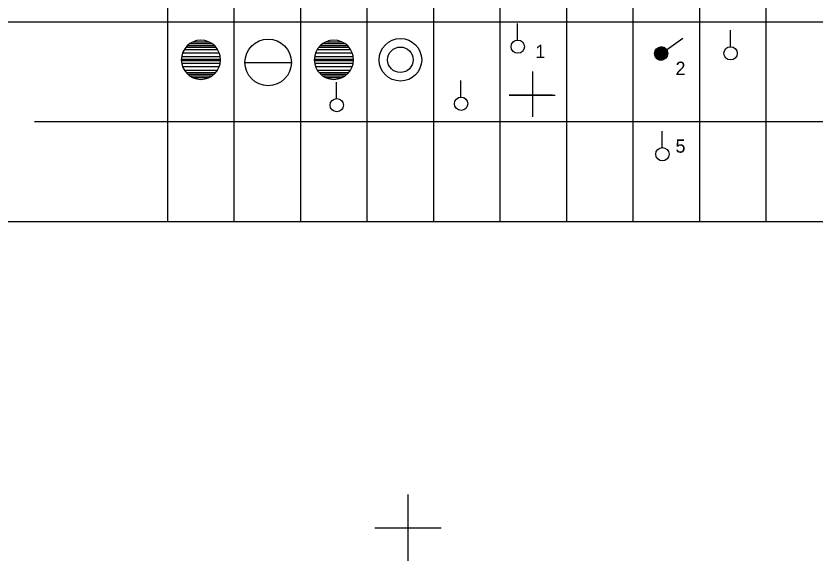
# Model space of a CAD drawing. Extents: x -28 to 822, y 61 to 665.
# Drawn here: x 337.9 to 458, y 60.7 to 142.6 of the extents above; entities that cross this region are included whole.
import ezdxf

# ---------------------------------------------------------------- set-up
doc = ezdxf.new("R2010")
doc.units = 0
doc.layers.add('KOLEJIŠTĚ', color=7, linetype='Continuous')
doc.layers.add('Vrstva 60', color=7, linetype='Continuous')

# ---------------------------------------------------------------- blocks, each defined once
blk = doc.blocks.new('HR6')
for p, q in [((-1.304, 1.895), (1.304, 1.895)), ((-0.95, 2.095), (0.95, 2.095)), ((-1.962, 1.2), (1.962, 1.2)), ((-1.748, 1.495), (1.748, 1.495)), ((-1.555, 1.695), (1.555, 1.695)), ((-2.265, 0.4), (2.265, 0.4)), ((-2.2, 0.09), (2.2, 0.09)), ((-2.156, 0.8), (2.156, 0.8)), ((-2.265, -0.4), (2.265, -0.4)), ((-2.2, -0.09), (2.2, -0.09)), ((-2.156, -0.8), (2.156, -0.8)), ((-1.962, -1.2), (1.962, -1.2)), ((-1.748, -1.495), (1.748, -1.495)), ((-1.555, -1.695), (1.555, -1.695)), ((-1.304, -1.895), (1.304, -1.895)), ((-0.95, -2.095), (0.95, -2.095))]:
    blk.add_line(p, q)
for start, end in [(0, 180), (180, 0)]:
    blk.add_arc((0, 0), 2.3, start, end)
blk = doc.blocks.new('ZT75')
at = {"xscale": 0.8, "yscale": 0.8000000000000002}
blk.add_blockref('HR6', (0, 0), dxfattribs=at)
blk = doc.blocks.new('HR1')
blk.add_line((-2.5, 0), (2.5, 0))
blk.add_circle((0, 0), 2.5)
blk = doc.blocks.new('HR3')
for radius in [2.5, 1.5]:
    blk.add_circle((0, 0), radius)
blk = doc.blocks.new('ZT72')
at = {"xscale": 0.8, "yscale": 0.8000000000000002}
blk.add_blockref('HR3', (0, 0), dxfattribs=at)
blk = doc.blocks.new('_X10')
for p, q in [((370.45, 480.11), (371.52, 481.17)), ((370.45, 480.13), (371.5, 481.17)), ((370.45, 480.14), (371.48, 481.17)), ((370.45, 480.16), (371.46, 481.17)), ((370.45, 480.18), (371.45, 481.17)), ((370.45, 480.2), (371.43, 481.17)), ((370.45, 480.21), (371.41, 481.17)), ((370.45, 480.23), (371.39, 481.17)), ((370.46, 480.06), (371.56, 481.17)), ((370.46, 480.08), (371.55, 481.17)), ((370.46, 480.09), (371.53, 481.17)), ((370.46, 480.25), (371.37, 481.17)), ((370.46, 480.27), (371.35, 481.17)), ((370.46, 480.29), (371.33, 481.17)), ((370.46, 480.01), (371.61, 481.16)), ((370.46, 480.03), (371.6, 481.16)), ((370.46, 480.04), (371.58, 481.16)), ((370.46, 480.31), (371.31, 481.16)), ((370.46, 480.33), (371.29, 481.16)), ((370.47, 480), (371.63, 481.16)), ((370.47, 480.35), (371.27, 481.16)), ((370.47, 479.97), (371.66, 481.15)), ((370.47, 479.98), (371.64, 481.15)), ((370.47, 480.37), (371.25, 481.15)), ((370.48, 479.95), (371.67, 481.15)), ((370.48, 480.4), (371.23, 481.15)), ((370.48, 479.93), (371.7, 481.14)), ((370.48, 479.94), (371.68, 481.14)), ((370.48, 480.42), (371.2, 481.14)), ((370.49, 479.91), (371.71, 481.14)), ((370.49, 479.88), (371.74, 481.13)), ((370.49, 479.9), (371.73, 481.13)), ((370.49, 480.45), (371.18, 481.13)), ((370.5, 479.87), (371.75, 481.13)), ((370.5, 480.47), (371.15, 481.13)), ((370.5, 479.86), (371.77, 481.12)), ((370.51, 479.84), (371.78, 481.12)), ((370.51, 480.5), (371.13, 481.12)), ((370.51, 479.83), (371.79, 481.11)), ((370.52, 479.82), (371.81, 481.11)), ((370.52, 480.52), (371.1, 481.11)), ((370.52, 479.81), (371.82, 481.1)), ((370.53, 479.79), (371.83, 481.1)), ((370.53, 480.55), (371.07, 481.1)), ((370.53, 479.78), (371.84, 481.09)), ((370.54, 479.77), (371.86, 481.09)), ((370.54, 479.76), (371.87, 481.08)), ((370.54, 480.58), (371.04, 481.08)), ((370.55, 479.74), (371.88, 481.08)), ((370.55, 479.73), (371.89, 481.07)), ((370.56, 480.62), (371.01, 481.07)), ((370.56, 479.72), (371.9, 481.06)), ((370.57, 479.71), (371.92, 481.06)), ((370.57, 479.7), (371.93, 481.05)), ((370.58, 479.69), (371.94, 481.05)), ((370.58, 480.66), (370.97, 481.05)), ((370.59, 479.67), (371.95, 481.04)), ((370.59, 479.66), (371.96, 481.03)), ((370.6, 479.65), (371.97, 481.03)), ((370.6, 479.64), (371.98, 481.02)), ((370.6, 480.7), (370.93, 481.02)), ((370.61, 479.63), (371.99, 481.01)), ((370.62, 479.62), (372, 481.01)), ((370.63, 479.61), (372.02, 481)), ((370.63, 479.6), (372.03, 480.99)), ((370.64, 480.75), (370.87, 480.99)), ((370.64, 479.59), (372.04, 480.98)), ((370.65, 479.58), (372.05, 480.98)), ((370.66, 479.57), (372.06, 480.97)), ((370.66, 479.56), (372.07, 480.96)), ((370.67, 479.55), (372.08, 480.95)), ((370.68, 479.54), (372.09, 480.95)), ((370.69, 479.53), (372.1, 480.94)), ((370.7, 479.52), (372.11, 480.93)), ((370.7, 479.51), (372.11, 480.92)), ((370.71, 480.84), (370.79, 480.92)), ((370.71, 479.5), (372.12, 480.91)), ((370.72, 479.49), (372.13, 480.9)), ((370.73, 479.48), (372.14, 480.9)), ((370.74, 479.47), (372.15, 480.89)), ((370.75, 479.46), (372.16, 480.88)), ((370.76, 479.46), (372.17, 480.87)), ((370.76, 479.45), (372.18, 480.86)), ((370.77, 479.44), (372.19, 480.85)), ((370.78, 479.43), (372.19, 480.84)), ((370.79, 479.42), (372.2, 480.83)), ((370.8, 479.41), (372.21, 480.82)), ((370.81, 479.4), (372.22, 480.81)), ((370.82, 479.4), (372.23, 480.8)), ((370.83, 479.39), (372.24, 480.79)), ((370.84, 479.38), (372.24, 480.78)), ((370.85, 479.37), (372.25, 480.77)), ((370.86, 479.37), (372.26, 480.76)), ((370.87, 479.36), (372.27, 480.75)), ((370.88, 479.35), (372.27, 480.74)), ((370.89, 479.34), (372.28, 480.73)), ((370.9, 479.34), (372.29, 480.72)), ((370.91, 479.33), (372.29, 480.71)), ((370.92, 479.32), (372.3, 480.7)), ((370.93, 479.32), (372.31, 480.69)), ((370.95, 479.31), (372.31, 480.68)), ((370.96, 479.3), (372.32, 480.67)), ((370.97, 479.3), (372.33, 480.66)), ((370.98, 479.29), (372.33, 480.64)), ((370.99, 479.28), (372.34, 480.63)), ((371, 479.28), (372.35, 480.62)), ((371.01, 479.27), (372.35, 480.61)), ((371.03, 479.27), (372.36, 480.6)), ((371.04, 479.26), (372.36, 480.59)), ((371.05, 479.26), (372.37, 480.57)), ((371.06, 479.25), (372.37, 480.56)), ((371.08, 479.25), (372.38, 480.55)), ((371.09, 479.24), (372.38, 480.54)), ((371.1, 479.24), (372.39, 480.52)), ((371.11, 479.23), (372.39, 480.51)), ((371.13, 479.23), (372.4, 480.5)), ((371.14, 479.22), (372.4, 480.48)), ((371.15, 479.22), (372.41, 480.47)), ((371.17, 479.21), (372.41, 480.46)), ((371.18, 479.21), (372.41, 480.44)), ((371.2, 479.21), (372.42, 480.43)), ((371.21, 479.2), (372.42, 480.42)), ((371.22, 479.2), (372.43, 480.4)), ((371.24, 479.2), (372.43, 480.39)), ((371.25, 479.19), (372.43, 480.37)), ((371.27, 479.19), (372.43, 480.36)), ((371.28, 479.19), (372.44, 480.34)), ((371.3, 479.18), (372.44, 480.33)), ((371.31, 479.18), (372.44, 480.31)), ((371.33, 479.18), (372.44, 480.3)), ((371.34, 479.18), (372.45, 480.28)), ((371.36, 479.18), (372.45, 480.26)), ((371.38, 479.17), (372.45, 480.25)), ((371.39, 479.17), (372.45, 480.23)), ((371.41, 479.17), (372.45, 480.21)), ((371.43, 479.17), (372.45, 480.2)), ((371.44, 479.17), (372.45, 480.18)), ((371.46, 479.17), (372.45, 480.16)), ((371.48, 479.17), (372.45, 480.14)), ((371.5, 479.17), (372.45, 480.13)), ((371.52, 479.17), (372.45, 480.11)), ((371.54, 479.18), (372.45, 480.09)), ((371.56, 479.18), (372.45, 480.07)), ((371.58, 479.18), (372.44, 480.05)), ((371.6, 479.18), (372.44, 480.03)), ((371.62, 479.19), (372.44, 480.01)), ((371.64, 479.19), (372.43, 479.99)), ((371.66, 479.19), (372.43, 479.96)), ((371.68, 479.2), (372.42, 479.94)), ((371.71, 479.21), (372.42, 479.92)), ((371.73, 479.21), (372.41, 479.89)), ((371.76, 479.22), (372.4, 479.87)), ((371.78, 479.23), (372.4, 479.84)), ((371.81, 479.24), (372.39, 479.81)), ((371.84, 479.25), (372.37, 479.78)), ((371.87, 479.27), (372.36, 479.75)), ((371.91, 479.28), (372.34, 479.72)), ((371.95, 479.3), (372.32, 479.68)), ((371.99, 479.33), (372.29, 479.63)), ((372.05, 479.37), (372.26, 479.58))]:
    blk.add_line(p, q)

msp = doc.modelspace()

# ---------------------------------------------------------------- linework, layer by layer
for p, q in [((360.62, 381.74), (360.62, 111.74)), ((370.62, 381.74), (370.62, 111.74)), ((380.62, 381.74), (380.62, 111.74)), ((390.62, 381.74), (390.62, 111.74)), ((400.62, 381.74), (400.62, 111.74)), ((410.62, 381.74), (410.62, 111.74)), ((410.62, 381.74), (410.62, 111.74)), ((420.62, 381.74), (420.62, 111.74)), ((430.62, 381.74), (430.62, 111.74)), ((440.62, 381.74), (440.62, 111.74)), ((450.62, 381.74), (450.62, 111.74)), ((5.07, 141.74), (540.62, 141.74)), ((413.28, 138.94), (413.28, 141.47)), ((445.28, 137.94), (445.28, 140.47)), ((435.68, 137.55), (438.13, 139.28)), ((415.54, 134.27), (415.54, 127.47)), ((386.06, 130.15), (386.06, 132.68)), ((404.76, 130.37), (404.76, 132.9)), ((340.62, 126.74), (540.62, 126.74)), ((435.02, 122.77), (435.02, 125.31)), ((5.07, 111.74), (540.62, 111.74))]:
    msp.add_line(p, q)
msp.add_lwpolyline([(412.94, 130.72), (418.54, 130.72), (412, 130.72), (418.96, 130.72)])
for centre in [(413.31, 138), (434.87, 136.97), (445.31, 137), (386.09, 129.21), (404.79, 129.43), (435.06, 121.84)]:
    msp.add_circle(centre, 1)
at = {"layer": 'Vrstva 60'}
for p, q in [((396.81, 60.73), (396.81, 70.73)), ((391.81, 65.73), (401.81, 65.73))]:
    msp.add_line(p, q, dxfattribs=at)

# ---------------------------------------------------------------- block references
at = {"xscale": 1.4000000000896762, "yscale": 1.4000000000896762}
msp.add_blockref('HR1', (375.78, 135.64), dxfattribs=at)
at = {"rotation": -92.29148628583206}
msp.add_blockref('_X10', (-30.07, 527.32), dxfattribs=at)
at = {"layer": 'KOLEJIŠTĚ', "xscale": 1.600000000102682, "yscale": 1.600000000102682}
for name, p in [('ZT75', (365.66, 136.03)), ('ZT75', (385.66, 136.03)), ('ZT72', (395.66, 136.03))]:
    msp.add_blockref(name, p, dxfattribs=at)

# ---------------------------------------------------------------- texts
for s, p in [('1', (415.97, 136.28)), ('2', (437.04, 133.75)), ('5', (437.04, 122.07))]:
    msp.add_text(s, height=2).set_placement(p)

doc.saveas('drawing.dxf')
